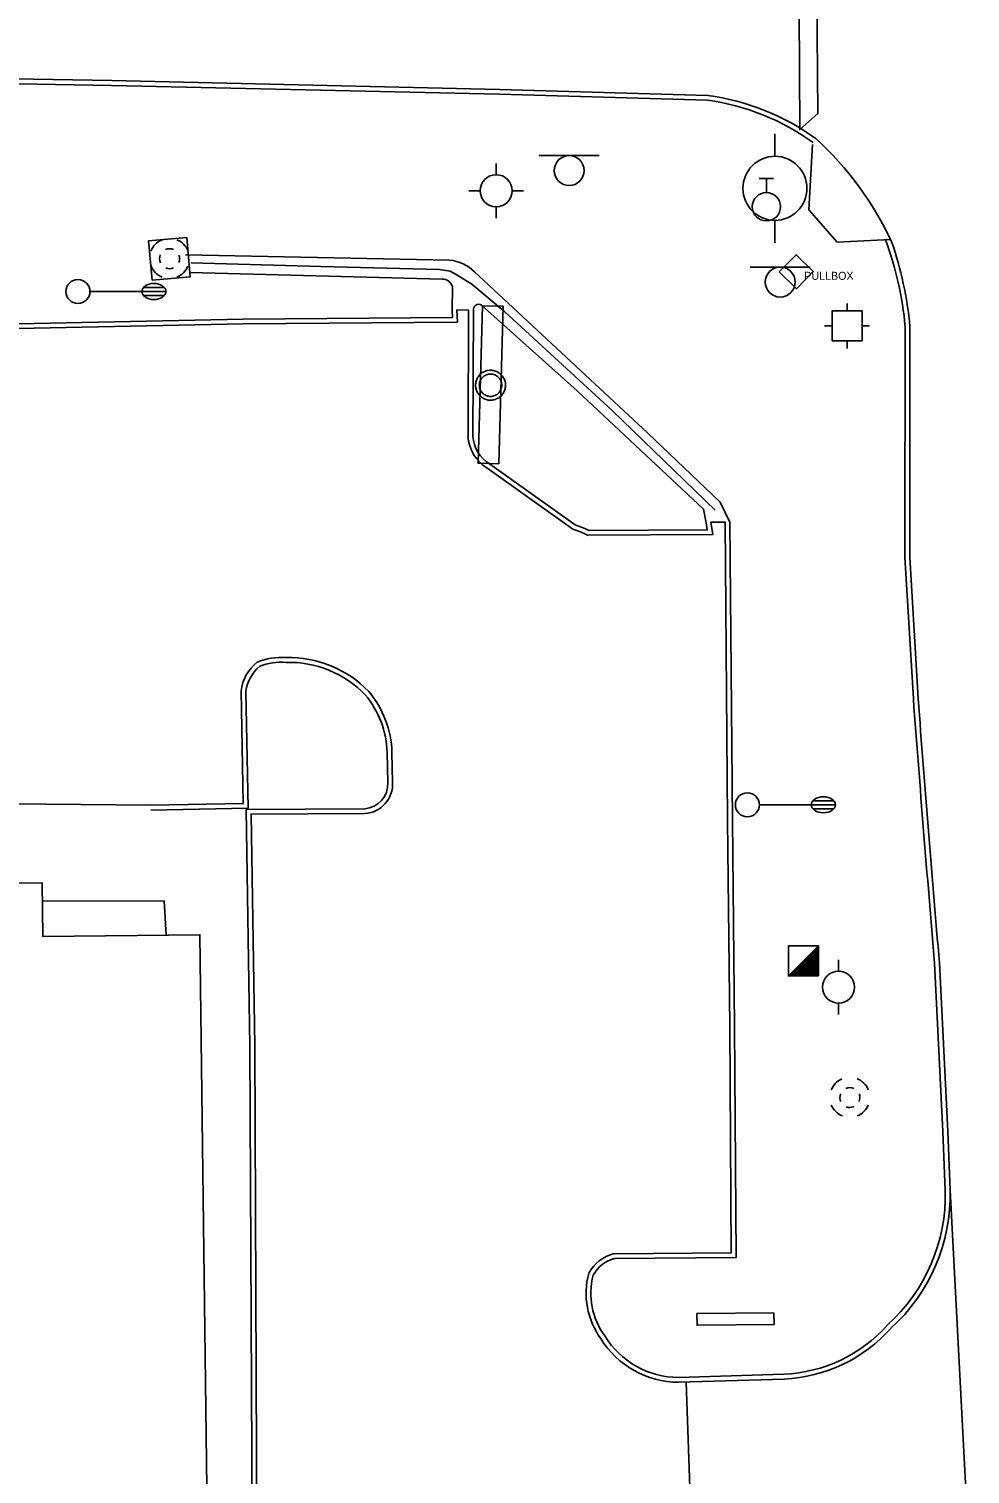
# Model space of a CAD drawing. Extents: x 2145380 to 2156929, y 139568 to 149130.
# Drawn here: x 2145500.8 to 2145618.4, y 142721.6 to 142902.2 of the extents above; entities that cross this region are included whole.
import ezdxf

# ---------------------------------------------------------------- set-up
doc = ezdxf.new("R2010")
doc.units = 0
for name, color, linetype in [('Default', 7, 'Continuous'), ('TOPO_Asphalt', 7, 'Continuous'), ('TOPO_Building', 7, 'Continuous'), ('TOPO_Concrete', 7, 'Continuous'), ('TOPO_Curb Back', 7, 'Continuous'), ('TOPO_DRAIN_Manhole', 7, 'Continuous'), ('TOPO_Flowline', 7, 'Continuous'), ('TOPO_Light Pole', 7, 'Continuous'), ('TOPO_Misc', 7, 'Continuous'), ('TOPO_Misc Line', 7, 'Continuous'), ('TOPO_Power Pole', 7, 'Continuous'), ('TOPO_Power Pullbox', 7, 'Continuous'), ('TOPO_Sidewalk', 7, 'Continuous'), ('TOPO_Sign', 7, 'Continuous'), ('TOPO_Traffic Signal', 7, 'Continuous'), ('TOPO_Wall Freestanding', 7, 'Continuous'), ('TOPO_Water Fire Hydrant', 7, 'Continuous'), ('TOPO_Water Valve', 7, 'Continuous')]:
    doc.layers.add(name, color=color, linetype=linetype)

# ---------------------------------------------------------------- blocks, each defined once
blk = doc.blocks.new('MHEXST')
at = {"layer": 'TOPO_DRAIN_Manhole'}
for centre, radius, start, end in [((-0.14, 0.26), 12.7, 112.97475, 158.26364), ((-0.14, 0.26), 12.7, 22.07441, 68.69913), ((-0.08, 0.11), 6.35, 157.97219, 204.16105), ((-0.08, 0.11), 6.35, 66.19406, 113.69103), ((-0.08, 0.11), 6.35, 336.80229, 21.40458), ((-0.14, 0.26), 12.7, 202.6921, 248.19382), ((-0.08, 0.11), 6.35, 248.57914, 293.19947), ((-0.14, 0.26), 12.7, 291.79631, 337.30323)]:
    blk.add_arc(centre, radius, start, end, dxfattribs=at)
blk = doc.blocks.new('TRFSIG')
at = {"layer": 'TOPO_Traffic Signal'}
for p, q in [((0.04, 4.66), (0.04, 7.04)), ((-4.7, -0.09), (-7.08, -0.09)), ((4.79, -0.09), (7.17, -0.09)), ((0.04, -4.83), (0.04, -7.22))]:
    blk.add_line(p, q, dxfattribs=at)
blk.add_lwpolyline([(-4.7, -4.85), (4.81, -4.83), (4.79, 4.67), (-4.72, 4.66), (-4.7, -4.85)], dxfattribs=at)
blk = doc.blocks.new('POWPOL')
at = {"layer": 'TOPO_Power Pole'}
for p, q in [((0, 10.16), (0, 17.34)), ((0, -10.16), (0, -17.34))]:
    blk.add_line(p, q, dxfattribs=at)
blk.add_circle((0, 0), 10.16, dxfattribs=at)
blk = doc.blocks.new('LP')
at = {"layer": 'TOPO_Light Pole'}
blk.add_line((3.81, 0), (20.32, 0), dxfattribs=at)
for points in [[(20.32, 0), (27.94, 0)], [(20.32, 0), (23.5, 0)], [(20.83, 1.27), (27.43, 1.27)], [(20.83, 1.27), (23.5, 1.27)], [(23.71, 1.27), (27.43, 1.27)], [(23.71, 0), (27.94, 0)], [(20.83, -1.27), (27.43, -1.27)], [(20.83, -1.27), (23.5, -1.27)], [(23.71, -1.27), (27.43, -1.27)]]:
    blk.add_lwpolyline(points, dxfattribs=at)
blk.add_circle((0, 0), 3.81, dxfattribs=at)
blk.add_ellipse((24.13, 0), major_axis=(3.81, 0), ratio=0.666667, dxfattribs=at)
blk = doc.blocks.new('FIRHYD')
at = {"layer": 'TOPO_Water Fire Hydrant'}
for p, q in [((-0.02, 10.16), (-0.03, 17.34)), ((10.16, 0.02), (17.34, 0.03)), ((-10.16, -0.02), (-17.34, -0.03)), ((0.02, -10.16), (0.03, -17.34))]:
    blk.add_line(p, q, dxfattribs=at)
blk.add_circle((0, 0), 10.16, dxfattribs=at)
blk = doc.blocks.new('pulbox')
at = {"layer": 'Default'}
blk.add_lwpolyline([(-5.38, -0.01), (-0.02, 5.42), (5.4, 0.06), (0.05, -5.36), (-5.38, -0.01)], dxfattribs=at)
blk.add_text('PULLBOX', height=2.54, dxfattribs=at).set_placement((2.54, -2.54))
blk = doc.blocks.new('WATVAL')
at = {"layer": 'Default'}
for p, q in [((-2.25, 9), (2.25, 9)), ((0, 4.5), (0, 9))]:
    blk.add_line(p, q, dxfattribs=at)
blk.add_circle((0, 0), 4.5, dxfattribs=at)

msp = doc.modelspace()

# ---------------------------------------------------------------- linework, layer by layer
at = {"layer": 'TOPO_Asphalt'}
for p, q in [((2145555.76, 142867.01), (2145554.3, 142867.05)), ((2145587.81, 142840.56), (2145586.03, 142840.56)), ((2145582.94, 142733.1), (2145583.79, 142709.09))]:
    msp.add_line(p, q, dxfattribs=at)
for points in [[(2145516.03, 142805.16), (2145494.13, 142805.39), (2145473.42, 142804.96)], [(2145615.93, 142757.07), (2145618.44, 142709.32), (2145618.12, 142684.28), (2145615.32, 142684.49)]]:
    msp.add_lwpolyline(points, dxfattribs=at)
msp.add_arc((2145571.48, 142858.21), 41.01, 25.0396, 47.5219, dxfattribs=at)
at = {"layer": 'TOPO_Building'}
msp.add_lwpolyline([(2145523.03, 142719.89), (2145435.01, 142718.8), (2145434.12, 142790.75), (2145458.79, 142791.05), (2145458.76, 142793.52), (2145480.91, 142793.8), (2145480.89, 142795.21), (2145502.47, 142795.47), (2145502.55, 142788.75), (2145522.18, 142788.99)], close=True, dxfattribs=at)
at = {"layer": 'TOPO_Concrete'}
for points in [[(2145553.38, 142873.27), (2145520.37, 142873.96)], [(2145520.91, 142871.73), (2145552.46, 142870.92)], [(2145588.41, 142840.56), (2145587.2, 142843.03), (2145578.14, 142851.64), (2145556.51, 142871.83)], [(2145553.75, 142869.95), (2145553.7, 142867.02)], [(2145557.38, 142867.67), (2145569.34, 142856.94), (2145585.12, 142842.17), (2145585.44, 142840.46)]]:
    msp.add_lwpolyline(points, dxfattribs=at)
for centre, radius, start, end in [((2145553, 142868.32), 4.96, 45.0475, 85.6788), ((2145552.45, 142869.57), 1.35, 16.2443, 89.7129), ((2145557.03, 142867.1), 0.67, 58.1487, 187.8944)]:
    msp.add_arc(centre, radius, start, end, dxfattribs=at)
at = {"layer": 'TOPO_Curb Back'}
for points in [[(2145453.99, 142896.6), (2145462.11, 142896.56), (2145511.15, 142895.71), (2145559.62, 142894.62), (2145585.66, 142893.86)], [(2145454.05, 142896), (2145462.11, 142895.96), (2145511.14, 142895.11), (2145559.61, 142894.02), (2145585.61, 142893.26)], [(2145553.7, 142867.02), (2145553.74, 142866.13), (2145527.58, 142865.9), (2145497.4, 142865.28), (2145465.98, 142865.34), (2145447.39, 142864.95), (2145447.78, 142850.2)], [(2145554.3, 142867.05), (2145554.36, 142865.53), (2145527.59, 142865.3), (2145497.41, 142864.68), (2145465.99, 142864.74), (2145448.01, 142864.36), (2145448.38, 142850.13)], [(2145555.69, 142851.23), (2145555.76, 142867.01)], [(2145556.29, 142851.25), (2145556.36, 142867.01)], [(2145610.32, 142864.96), (2145610.3, 142836.15), (2145611.35, 142818.47)], [(2145610.92, 142864.99), (2145610.9, 142836.16), (2145611.95, 142818.51)], [(2145568.78, 142839.67), (2145558.04, 142847.34)], [(2145569.06, 142840.21), (2145558.37, 142847.84)], [(2145586.03, 142840.56), (2145586.28, 142838.98), (2145570.67, 142838.9)], [(2145585.44, 142840.46), (2145585.58, 142839.58), (2145570.81, 142839.5)], [(2145573.94, 142749.14), (2145588.58, 142749.26), (2145588.41, 142777.54), (2145588.13, 142803.3), (2145587.81, 142840.56)], [(2145574.02, 142748.54), (2145589.19, 142748.66), (2145589.01, 142777.54), (2145588.73, 142803.3), (2145588.41, 142840.56)], [(2145516.03, 142805.16), (2145527.59, 142805.38), (2145527.33, 142819.45)], [(2145516.04, 142804.56), (2145528.2, 142804.79), (2145527.93, 142819.42)], [(2145545.57, 142811.76), (2145545.66, 142808)], [(2145546.17, 142811.77), (2145546.26, 142808.03)], [(2145542.77, 142804.73), (2145527.97, 142804.65), (2145528.43, 142775.08), (2145528.65, 142723.95), (2145528.62, 142713.41), (2145544.16, 142713.55)], [(2145542.8, 142804.13), (2145528.58, 142804.06), (2145529.03, 142775.09), (2145529.25, 142723.95), (2145529.22, 142714.02), (2145544.15, 142714.15)], [(2145614.01, 142785.42), (2145615.05, 142764.39), (2145615.33, 142757.05)], [(2145614.6, 142785.46), (2145615.65, 142764.42), (2145615.93, 142757.07)], [(2145595.18, 142734.08), (2145582, 142733.67)], [(2145595.2, 142733.48), (2145582.01, 142733.07)]]:
    msp.add_lwpolyline(points, dxfattribs=at)
for centre, radius, start, end in [((2145581.44, 142863.67), 30.49, 54.4251, 82.0463), ((2145581.44, 142863.67), 29.89, 54.4251, 81.9834), ((2145568.97, 142861.29), 41.52, 5.0798, 20.4846), ((2145565.98, 142860.83), 45.13, 5.2936, 19.0672), ((2145560.64, 142851.57), 4.97, 183.8487, 238.4419), ((2145560.64, 142851.57), 4.37, 184.1227, 238.7049), ((2145564.33, 142826.1), 14.28, 63.618, 71.8219), ((2145564.33, 142826.1), 14.88, 64.1713, 71.4663), ((2145532.28, 142815.98), 7.66, 85.2644, 112.5928), ((2145533.34, 142809.86), 13.76, 43.7291, 91.7517), ((2145532.68, 142818.82), 5.39, 128.2721, 173.2577), ((2145532.68, 142818.82), 4.79, 129.2521, 172.7828), ((2145532.28, 142815.98), 7.06, 84.9911, 111.9159), ((2145533.34, 142809.86), 13.16, 43.8148, 91.9011), ((2145533.8, 142811.42), 11.78, 1.6329, 39.8814), ((2145533.8, 142811.42), 12.38, 1.6261, 39.9769), ((2148518.46, 143035.65), 2915.21, 184.27236, 184.92406), ((2148518.46, 143035.65), 2914.61, 184.27245, 184.92427), ((2145542.54, 142807.85), 3.13, 274.2907, 2.8818), ((2145542.54, 142807.85), 3.73, 273.9551, 2.7535), ((2145593.56, 142756.45), 21.78, 311.9253, 1.5765), ((2145593.56, 142756.45), 22.38, 312.0116, 1.5851), ((2145575.13, 142744.33), 4.96, 103.8348, 151.5946), ((2145575.13, 142744.33), 4.36, 104.7311, 150.6757), ((2145580.13, 142744.19), 9.69, 165.092, 215.7609), ((2145580.13, 142744.19), 9.09, 165.547, 215.8903), ((2145582.08, 142744.62), 11.55, 211.8314, 269.6555), ((2145582.08, 142744.62), 10.95, 211.7234, 269.5978), ((2145594.36, 142752.46), 18.4, 272.5365, 318.3664), ((2145594.36, 142752.46), 19, 272.5246, 318.2644)]:
    msp.add_arc(centre, radius, start, end, dxfattribs=at)
at = {"layer": 'TOPO_Flowline'}
msp.add_lwpolyline([(2145586.56, 142842.04), (2145573.7, 142854.49), (2145560.28, 142866.83), (2145556.17, 142870.28), (2145554.21, 142871.5), (2145553.47, 142871.89), (2145552.12, 142872.09), (2145537.28, 142872.47), (2145521.08, 142872.94)], dxfattribs=at)
at = {"layer": 'TOPO_Misc'}
for p, q in [((2145595.74, 142783.85), (2145599.48, 142787.6)), ((2145599.27, 142787.38), (2145599.48, 142787.38)), ((2145599.45, 142787.56), (2145599.48, 142787.56)), ((2145597.4, 142785.51), (2145599.48, 142785.51)), ((2145597.58, 142785.69), (2145599.48, 142785.69)), ((2145597.76, 142785.88), (2145599.48, 142785.88)), ((2145597.95, 142786.07), (2145599.48, 142786.07)), ((2145598.14, 142786.25), (2145599.48, 142786.25)), ((2145598.33, 142786.44), (2145599.48, 142786.44)), ((2145598.51, 142786.62), (2145599.48, 142786.62)), ((2145598.7, 142786.81), (2145599.48, 142786.81)), ((2145598.89, 142787), (2145599.48, 142787)), ((2145599.08, 142787.19), (2145599.48, 142787.19)), ((2145595.9, 142784.01), (2145599.48, 142784.01)), ((2145596.09, 142784.2), (2145599.48, 142784.2)), ((2145596.27, 142784.38), (2145599.48, 142784.38)), ((2145596.46, 142784.57), (2145599.48, 142784.57)), ((2145596.64, 142784.76), (2145599.48, 142784.76)), ((2145596.83, 142784.95), (2145599.48, 142784.95)), ((2145597.03, 142785.14), (2145599.48, 142785.14)), ((2145597.21, 142785.32), (2145599.48, 142785.32))]:
    msp.add_line(p, q, dxfattribs=at)
msp.add_lwpolyline([(2145599.48, 142783.85), (2145599.48, 142787.6), (2145595.73, 142787.59), (2145595.74, 142783.85), (2145599.48, 142783.85)], dxfattribs=at)
at = {"layer": 'TOPO_Misc Line'}
msp.add_lwpolyline([(2145599.13, 142926.61), (2145599.4, 142891.61), (2145597.15, 142889.6), (2145596.93, 142926.59)], close=True, dxfattribs=at)
at = {"layer": 'TOPO_Power Pole'}
for points in [[(2145556.62, 142857.65), (2145556.63, 142857.78), (2145556.65, 142857.91), (2145556.67, 142858.04), (2145556.71, 142858.17), (2145556.74, 142858.29), (2145556.79, 142858.42), (2145556.85, 142858.54), (2145556.92, 142858.65), (2145557, 142858.76), (2145557.08, 142858.86), (2145557.17, 142858.96), (2145557.26, 142859.06), (2145557.37, 142859.14), (2145557.47, 142859.22), (2145557.59, 142859.28), (2145557.71, 142859.34), (2145557.82, 142859.39), (2145557.95, 142859.44), (2145558.08, 142859.47), (2145558.22, 142859.5), (2145558.35, 142859.52), (2145558.48, 142859.52), (2145558.6, 142859.52), (2145558.73, 142859.5), (2145558.87, 142859.49), (2145558.99, 142859.45), (2145559.12, 142859.41), (2145559.24, 142859.36), (2145559.37, 142859.31), (2145559.48, 142859.25), (2145559.59, 142859.17), (2145559.69, 142859.09), (2145559.79, 142859.01), (2145559.88, 142858.91), (2145559.97, 142858.81), (2145560.05, 142858.7), (2145560.12, 142858.59), (2145560.18, 142858.47), (2145560.23, 142858.35), (2145560.28, 142858.22), (2145560.32, 142858.1), (2145560.35, 142857.96), (2145560.36, 142857.83), (2145560.37, 142857.7), (2145560.37, 142857.58), (2145560.36, 142857.44), (2145560.34, 142857.31), (2145560.31, 142857.18), (2145560.27, 142857.06), (2145560.23, 142856.93), (2145560.17, 142856.81), (2145560.11, 142856.7), (2145560.04, 142856.59), (2145559.96, 142856.48), (2145559.87, 142856.37), (2145559.77, 142856.28), (2145559.68, 142856.2), (2145559.57, 142856.12), (2145559.46, 142856.05), (2145559.34, 142855.98), (2145559.22, 142855.93), (2145559.1, 142855.88), (2145558.97, 142855.84), (2145558.84, 142855.81), (2145558.71, 142855.79), (2145558.58, 142855.78), (2145558.46, 142855.78), (2145558.32, 142855.79), (2145558.19, 142855.8), (2145558.06, 142855.83), (2145557.94, 142855.87), (2145557.81, 142855.91), (2145557.69, 142855.96), (2145557.57, 142856.03), (2145557.46, 142856.1), (2145557.35, 142856.18), (2145557.25, 142856.26), (2145557.15, 142856.35), (2145557.07, 142856.45), (2145556.98, 142856.56), (2145556.91, 142856.67), (2145556.84, 142856.78), (2145556.79, 142856.9), (2145556.73, 142857.03), (2145556.7, 142857.15), (2145556.67, 142857.27), (2145556.65, 142857.41), (2145556.63, 142857.54), (2145556.62, 142857.65)], [(2145557.09, 142857.65), (2145557.1, 142857.76), (2145557.12, 142857.88), (2145557.14, 142857.99), (2145557.17, 142858.1), (2145557.21, 142858.21), (2145557.26, 142858.31), (2145557.32, 142858.4), (2145557.39, 142858.5), (2145557.46, 142858.59), (2145557.54, 142858.67), (2145557.63, 142858.75), (2145557.72, 142858.81), (2145557.82, 142858.87), (2145557.92, 142858.92), (2145558.02, 142858.97), (2145558.13, 142859.01), (2145558.25, 142859.03), (2145558.36, 142859.05), (2145558.48, 142859.05), (2145558.59, 142859.05), (2145558.7, 142859.04), (2145558.82, 142859.02), (2145558.92, 142858.98), (2145559.03, 142858.95), (2145559.14, 142858.9), (2145559.23, 142858.84), (2145559.33, 142858.78), (2145559.42, 142858.71), (2145559.5, 142858.63), (2145559.58, 142858.54), (2145559.65, 142858.45), (2145559.71, 142858.35), (2145559.77, 142858.25), (2145559.81, 142858.15), (2145559.85, 142858.04), (2145559.88, 142857.93), (2145559.89, 142857.81), (2145559.9, 142857.7), (2145559.9, 142857.59), (2145559.89, 142857.48), (2145559.87, 142857.36), (2145559.85, 142857.25), (2145559.8, 142857.14), (2145559.76, 142857.04), (2145559.71, 142856.94), (2145559.64, 142856.84), (2145559.58, 142856.75), (2145559.5, 142856.67), (2145559.42, 142856.59), (2145559.32, 142856.51), (2145559.22, 142856.46), (2145559.13, 142856.4), (2145559.02, 142856.35), (2145558.92, 142856.31), (2145558.8, 142856.28), (2145558.69, 142856.26), (2145558.57, 142856.25), (2145558.47, 142856.25), (2145558.35, 142856.26), (2145558.24, 142856.27), (2145558.12, 142856.29), (2145558.02, 142856.33), (2145557.92, 142856.37), (2145557.81, 142856.43), (2145557.72, 142856.49), (2145557.62, 142856.56), (2145557.53, 142856.63), (2145557.45, 142856.72), (2145557.38, 142856.81), (2145557.31, 142856.9), (2145557.26, 142857), (2145557.21, 142857.1), (2145557.17, 142857.21), (2145557.14, 142857.32), (2145557.12, 142857.43), (2145557.1, 142857.55), (2145557.09, 142857.65)]]:
    msp.add_lwpolyline(points, dxfattribs=at)
at = {"layer": 'TOPO_Sidewalk'}
for points in [[(2145608.51, 142875.85), (2145601.83, 142875.52), (2145598.27, 142879.57), (2145598.73, 142887.71)], [(2145517.94, 142788.94), (2145517.69, 142793.21), (2145502.5, 142793.17)]]:
    msp.add_lwpolyline(points, dxfattribs=at)
at = {"layer": 'TOPO_Sign'}
for points in [[(2145564.58, 142886.34), (2145572.08, 142886.35)], [(2145568.33, 142886.34), (2145568.33, 142886.34)], [(2145566.47, 142884.47), (2145566.47, 142884.47)], [(2145570.2, 142884.47), (2145570.2, 142884.47)], [(2145568.33, 142882.6), (2145568.33, 142882.6)], [(2145590.96, 142872.41), (2145598.45, 142872.42)], [(2145594.71, 142872.41), (2145594.71, 142872.41)], [(2145592.84, 142870.54), (2145592.84, 142870.54)], [(2145596.58, 142870.54), (2145596.58, 142870.54)], [(2145594.71, 142868.68), (2145594.71, 142868.68)]]:
    msp.add_lwpolyline(points, dxfattribs=at)
for points in [[(2145560.08, 142867.52), (2145559.53, 142847.83), (2145556.95, 142847.9), (2145557.5, 142867.59)], [(2145593.93, 142741.74), (2145584.3, 142741.65), (2145584.31, 142740.2), (2145593.94, 142740.28)]]:
    msp.add_lwpolyline(points, close=True, dxfattribs=at)
for centre, start, end in [((2145568.33, 142884.47), 90, 180), ((2145568.33, 142884.47), 360, 90), ((2145568.33, 142884.47), 180, 270), ((2145568.33, 142884.47), 270, 0), ((2145594.71, 142870.54), 90, 180), ((2145594.71, 142870.54), 360, 90), ((2145594.71, 142870.54), 180, 270), ((2145594.71, 142870.54), 270, 0)]:
    msp.add_arc(centre, 1.87, start, end, dxfattribs=at)
at = {"layer": 'TOPO_Wall Freestanding'}
msp.add_lwpolyline([(2145516.19, 142870.79), (2145515.76, 142875.7), (2145520.53, 142876.12), (2145520.96, 142871.21)], close=True, dxfattribs=at)

# ---------------------------------------------------------------- block references
at = {"layer": 'TOPO_DRAIN_Manhole', "xscale": 0.19685000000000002, "yscale": 0.19685000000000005}
for p in [(2145518.4, 142873.44), (2145603.43, 142768.63)]:
    msp.add_blockref('MHEXST', p, dxfattribs=at)
at = {"layer": 'TOPO_Light Pole', "xscale": 0.39370000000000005, "yscale": 0.3937000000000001}
for p in [(2145506.93, 142869.36), (2145590.6, 142805.23)]:
    msp.add_blockref('LP', p, dxfattribs=at)
at = {"layer": 'TOPO_Power Pole'}
for p, xscale, yscale in [((2145594.05, 142882.25), 0.39370000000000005, 0.3937000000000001), ((2145602, 142782.44), 0.19685000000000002, 0.19685000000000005)]:
    msp.add_blockref('POWPOL', p, dxfattribs=dict(at, xscale=xscale, yscale=yscale))
at = {"layer": 'TOPO_Power Pullbox', "xscale": 0.39370000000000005, "yscale": 0.3937000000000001}
msp.add_blockref('pulbox', (2145596.71, 142871.82), dxfattribs=at)
at = {"layer": 'TOPO_Traffic Signal', "xscale": 0.39370000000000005, "yscale": 0.3937000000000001}
msp.add_blockref('TRFSIG', (2145603.05, 142865.1), dxfattribs=at)
at = {"layer": 'TOPO_Water Fire Hydrant', "xscale": 0.19685000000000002, "yscale": 0.19685000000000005}
msp.add_blockref('FIRHYD', (2145559.21, 142881.95), dxfattribs=at)
at = {"layer": 'TOPO_Water Valve', "xscale": 0.39370000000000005, "yscale": 0.3937000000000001}
msp.add_blockref('WATVAL', (2145592.98, 142879.95), dxfattribs=at)

doc.saveas('drawing.dxf')
